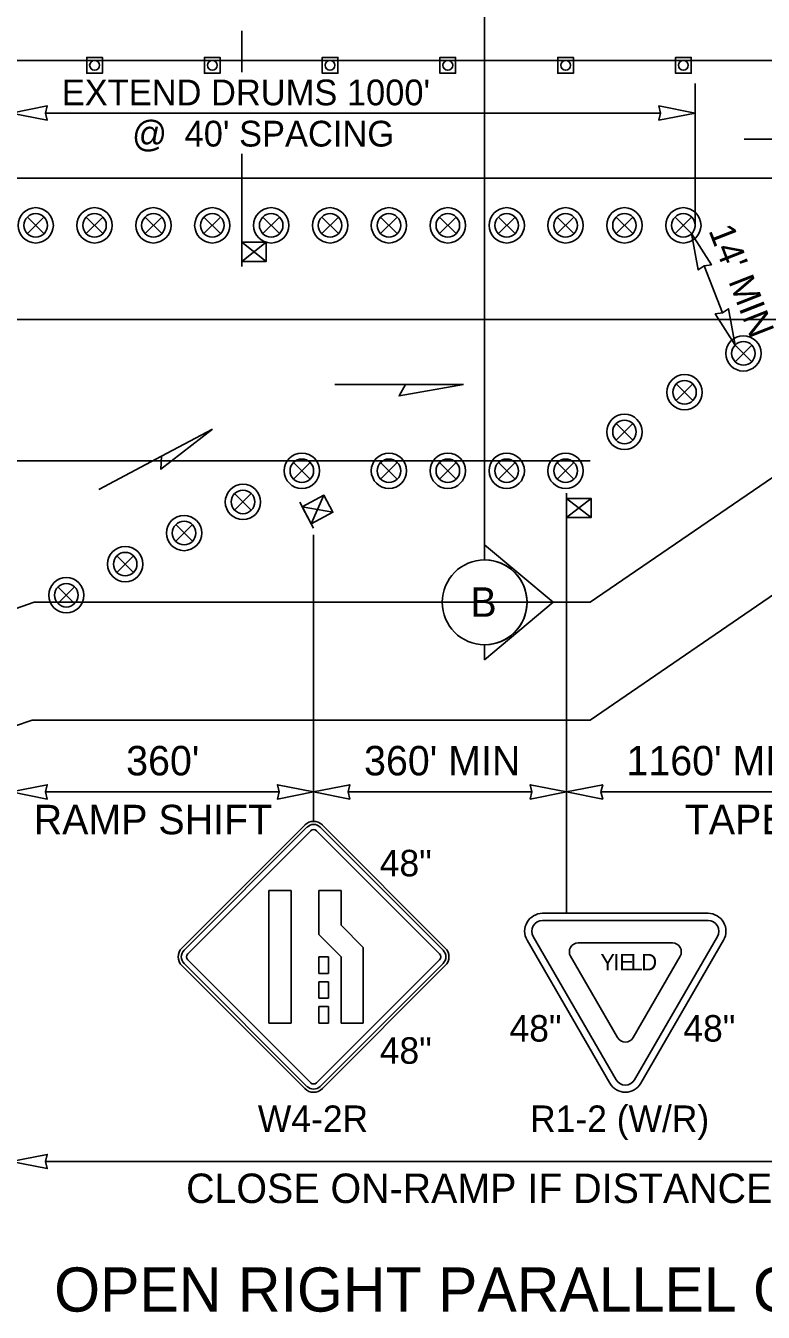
# Model space of a CAD drawing. Extents: x 99999 to 100116, y 99995 to 100013.
# Drawn here: x 100050.642 to 100052.647, y 100004.799 to 100008.293 of the extents above; entities that cross this region are included whole.
import ezdxf

# ---------------------------------------------------------------- set-up
doc = ezdxf.new("R2010")
doc.units = 0
for name, color, linetype in [('RD_MK_LineEdgeYellow', 7, 'Continuous'), ('RD_MK_LineLane', 7, 'Continuous'), ('SH_DE_DetailHeading2Text', 7, 'Continuous'), ('SH_GI_SectionCut', 7, 'Continuous'), ('TR_SN_ConstructionSigns', 7, 'Continuous'), ('TR_WZ_PortableSignMount5ftMinBlk-Org', 7, 'Continuous'), ('TR_WZ_PortableSignMount5ftMinRed-Wht', 7, 'Continuous'), ('TR_WZ_TrafficCone', 7, 'Continuous'), ('TR_WZ_TrafficSafetyDrum', 7, 'Continuous'), ('TR_WZ_WorkZoneDetails', 7, 'Continuous'), ('TR_WZ_WorkZoneTextCurrent', 7, 'Continuous')]:
    doc.layers.add(name, color=color, linetype=linetype)

msp = doc.modelspace()

# ---------------------------------------------------------------- linework, layer by layer
at = {"layer": 'RD_MK_LineEdgeYellow'}
for p, q in [((100048.195, 100007.8789), (100055.43, 100007.8789)), ((100052.1758, 100006.7269), (100052.7368, 100007.1109)), ((100050.6655, 100006.7269), (100048.195, 100005.8927)), ((100050.6655, 100006.7269), (100052.1758, 100006.7269))]:
    msp.add_line(p, q, dxfattribs=at)
at = {"layer": 'RD_MK_LineLane'}
for points in [[(100055.43, 100007.4949), (100048.195, 100007.4949)], [(100052.1758, 100007.1109), (100050.6024, 100007.1109)], [(100052.1758, 100007.1109), (100050.6024, 100007.1109)]]:
    msp.add_lwpolyline(points, dxfattribs=at)
at = {"layer": 'SH_GI_SectionCut'}
for p, q in [((100051.8894, 100008.3179), (100051.8894, 100006.8828)), ((100051.8894, 100006.8828), (100051.8894, 100006.8421)), ((100052.0755, 100006.7269), (100051.8894, 100006.8828)), ((100051.8894, 100006.571), (100052.0755, 100006.7269)), ((100051.8894, 100006.6117), (100051.8894, 100006.571))]:
    msp.add_line(p, q, dxfattribs=at)
msp.add_circle((100051.8894, 100006.7269), 0.1152, dxfattribs=at)
for start, end in [(0, 269.9978), (269.9978, 90.0022), (269.9978, 0)]:
    msp.add_arc((100051.8894, 100006.7269), 0.1152, start, end, dxfattribs=at)
at = {"layer": 'TR_SN_ConstructionSigns'}
for p, q in [((100051.4008, 100006.122), (100051.0667, 100005.7879)), ((100051.4067, 100006.1161), (100051.0726, 100005.7819)), ((100051.7766, 100005.7819), (100051.4425, 100006.1161)), ((100051.7826, 100005.7879), (100051.4485, 100006.122)), ((100051.0826, 100005.772), (100051.4167, 100006.1061)), ((100051.4326, 100006.1061), (100051.7667, 100005.772)), ((100051.303, 100005.944), (100051.3634, 100005.944)), ((100051.303, 100005.584), (100051.303, 100005.944)), ((100051.3634, 100005.944), (100051.303, 100005.944)), ((100051.303, 100005.944), (100051.303, 100005.584)), ((100051.3634, 100005.944), (100051.3634, 100005.584)), ((100051.3634, 100005.584), (100051.3634, 100005.944)), ((100051.4387, 100005.944), (100051.4992, 100005.944)), ((100051.4387, 100005.8245), (100051.4387, 100005.944)), ((100051.4992, 100005.944), (100051.4387, 100005.944)), ((100051.4387, 100005.944), (100051.4387, 100005.8245)), ((100051.4992, 100005.944), (100051.4992, 100005.8496)), ((100051.4992, 100005.8496), (100051.4992, 100005.944)), ((100052.4966, 100005.8822), (100052.0469, 100005.8822)), ((100051.4992, 100005.8496), (100051.5596, 100005.7891)), ((100051.5596, 100005.7891), (100051.4992, 100005.8496)), ((100052.0469, 100005.8627), (100052.0469, 100005.8629)), ((100052.0469, 100005.8629), (100052.2718, 100005.8629)), ((100052.2718, 100005.8629), (100052.0469, 100005.8629)), ((100052.0469, 100005.8629), (100052.0469, 100005.8627)), ((100051.4992, 100005.764), (100051.4387, 100005.8245)), ((100051.4387, 100005.8245), (100051.4992, 100005.764)), ((100052.2296, 100005.4205), (100052.0048, 100005.8091)), ((100052.0048, 100005.8091), (100052.2296, 100005.4205)), ((100052.2465, 100005.4302), (100052.0216, 100005.8189)), ((100052.0216, 100005.8189), (100052.2465, 100005.4302)), ((100052.2718, 100005.802), (100052.144, 100005.802)), ((100052.144, 100005.802), (100052.2718, 100005.802)), ((100052.3995, 100005.802), (100052.2718, 100005.802)), ((100052.2718, 100005.802), (100052.3995, 100005.802)), ((100052.5219, 100005.8189), (100052.2971, 100005.4303)), ((100052.2971, 100005.4303), (100052.5219, 100005.8189)), ((100052.5387, 100005.8091), (100052.3139, 100005.4205)), ((100052.3139, 100005.4205), (100052.5387, 100005.8091)), ((100051.5596, 100005.7891), (100051.5596, 100005.584)), ((100051.5596, 100005.584), (100051.5596, 100005.7891)), ((100051.0667, 100005.7402), (100051.4008, 100005.4061)), ((100051.0726, 100005.7462), (100051.4067, 100005.412)), ((100051.4167, 100005.422), (100051.0826, 100005.7561)), ((100051.7667, 100005.7561), (100051.4326, 100005.422)), ((100051.4387, 100005.764), (100051.4654, 100005.764)), ((100051.4387, 100005.719), (100051.4387, 100005.764)), ((100051.4654, 100005.764), (100051.4387, 100005.764)), ((100051.4387, 100005.764), (100051.4387, 100005.719)), ((100051.4425, 100005.412), (100051.7766, 100005.7462)), ((100051.4485, 100005.4061), (100051.7826, 100005.7402)), ((100051.4654, 100005.764), (100051.4654, 100005.719)), ((100051.4654, 100005.719), (100051.4654, 100005.764)), ((100051.4992, 100005.584), (100051.4992, 100005.764)), ((100051.4992, 100005.764), (100051.4992, 100005.584)), ((100052.1229, 100005.7654), (100052.2507, 100005.5445)), ((100052.2507, 100005.5445), (100052.1229, 100005.7654)), ((100052.2928, 100005.5445), (100052.4206, 100005.7654)), ((100052.4206, 100005.7654), (100052.2928, 100005.5445)), ((100051.4654, 100005.719), (100051.4387, 100005.719)), ((100051.4387, 100005.719), (100051.4654, 100005.719)), ((100051.4387, 100005.6965), (100051.4654, 100005.6965)), ((100051.4387, 100005.6515), (100051.4387, 100005.6965)), ((100051.4654, 100005.6965), (100051.4387, 100005.6965)), ((100051.4387, 100005.6965), (100051.4387, 100005.6515)), ((100051.4654, 100005.6965), (100051.4654, 100005.6515)), ((100051.4654, 100005.6515), (100051.4654, 100005.6965)), ((100051.4654, 100005.6515), (100051.4387, 100005.6515)), ((100051.4387, 100005.6515), (100051.4654, 100005.6515)), ((100051.4387, 100005.629), (100051.4654, 100005.629)), ((100051.4387, 100005.584), (100051.4387, 100005.629)), ((100051.4654, 100005.629), (100051.4387, 100005.629)), ((100051.4387, 100005.629), (100051.4387, 100005.584)), ((100051.4654, 100005.629), (100051.4654, 100005.584)), ((100051.4654, 100005.584), (100051.4654, 100005.629)), ((100051.3634, 100005.584), (100051.303, 100005.584)), ((100051.303, 100005.584), (100051.3634, 100005.584)), ((100051.4654, 100005.584), (100051.4387, 100005.584)), ((100051.4387, 100005.584), (100051.4654, 100005.584)), ((100051.5596, 100005.584), (100051.4992, 100005.584)), ((100051.4992, 100005.584), (100051.5596, 100005.584))]:
    msp.add_line(p, q, dxfattribs=at)
for points in [[(100052.0469, 100005.8822), (100052.4966, 100005.8822)], [(100052.2718, 100005.8629), (100052.4966, 100005.8629), (100052.4966, 100005.8627)], [(100052.4966, 100005.8627), (100052.4966, 100005.8629), (100052.2718, 100005.8629)]]:
    msp.add_lwpolyline(points, dxfattribs=at)
for centre, radius, start, end in [((100051.4246, 100006.0982), 0.0338, 45, 135), ((100051.4246, 100006.0982), 0.0253, 45, 135), ((100051.4246, 100006.0982), 0.0113, 45, 135), ((100052.0469, 100005.8335), 0.0487, 90, 210.0517), ((100052.0469, 100005.8335), 0.0487, 90, 210.0517), ((100052.4966, 100005.8335), 0.0487, 329.9522, 90), ((100052.4966, 100005.8335), 0.0487, 329.9522, 90), ((100052.0469, 100005.8335), 0.0292, 90, 210.0517), ((100052.0469, 100005.8335), 0.0292, 90, 210.0517), ((100052.4966, 100005.8335), 0.0292, 329.9522, 90), ((100052.4966, 100005.8335), 0.0292, 329.9522, 90), ((100052.144, 100005.7776), 0.0244, 90, 210.0513), ((100052.144, 100005.7776), 0.0244, 90, 210.0513), ((100052.3995, 100005.7776), 0.0244, 329.9514, 90), ((100052.3995, 100005.7776), 0.0244, 329.9514, 90), ((100051.0905, 100005.764), 0.0338, 135, 225), ((100051.0905, 100005.764), 0.0253, 135, 225), ((100051.0905, 100005.764), 0.0113, 135, 225), ((100051.7587, 100005.764), 0.0113, 315, 45), ((100051.7587, 100005.764), 0.0253, 315, 45), ((100051.7587, 100005.764), 0.0338, 315, 45), ((100052.2718, 100005.5567), 0.0244, 210.0519, 329.9525), ((100052.2718, 100005.5567), 0.0244, 210.0519, 329.9525), ((100051.4246, 100005.4299), 0.0113, 225, 315), ((100052.2718, 100005.4449), 0.0487, 210.0518, 329.9516), ((100052.2718, 100005.4449), 0.0487, 210.0518, 329.9516), ((100052.2718, 100005.4449), 0.0292, 210.0518, 329.9516), ((100052.2718, 100005.4449), 0.0292, 210.0518, 329.9516), ((100051.4246, 100005.4299), 0.0338, 225, 315), ((100051.4246, 100005.4299), 0.0253, 225, 315)]:
    msp.add_arc(centre, radius, start, end, dxfattribs=at)
at = {"layer": 'TR_WZ_PortableSignMount5ftMinBlk-Org'}
for p, q in [((100051.2294, 100007.6389), (100051.2294, 100007.7189)), ((100051.2961, 100007.7049), (100051.2294, 100007.6529)), ((100051.2961, 100007.6529), (100051.2294, 100007.7049)), ((100051.2627, 100007.6789), (100051.2627, 100007.6789)), ((100051.2628, 100007.679), (100051.2628, 100007.679)), ((100051.4246, 100006.9281), (100051.3873, 100006.9988)), ((100051.4528, 100007.0176), (100051.4181, 100006.9405)), ((100051.4771, 100006.9716), (100051.3938, 100006.9865)), ((100051.4354, 100006.9791), (100051.4354, 100006.9791)), ((100051.4355, 100006.9792), (100051.4355, 100006.9792))]:
    msp.add_line(p, q, dxfattribs=at)
for points in [[(100051.2961, 100007.7049), (100051.2961, 100007.6529), (100051.2294, 100007.6529), (100051.2294, 100007.7049)], [(100051.2294, 100007.6529), (100051.2961, 100007.6529), (100051.2961, 100007.7049), (100051.2294, 100007.7049)], [(100051.4528, 100007.0176), (100051.4771, 100006.9716), (100051.4181, 100006.9405), (100051.3938, 100006.9865)], [(100051.4181, 100006.9405), (100051.4771, 100006.9716), (100051.4528, 100007.0176), (100051.3938, 100006.9865)]]:
    msp.add_lwpolyline(points, close=True, dxfattribs=at)
at = {"layer": 'TR_WZ_PortableSignMount5ftMinRed-Wht'}
for p, q in [((100052.1119, 100006.9432), (100052.1119, 100007.0232)), ((100052.1786, 100007.0092), (100052.1119, 100006.9572)), ((100052.1786, 100006.9572), (100052.1119, 100007.0092)), ((100052.1452, 100006.9832), (100052.1452, 100006.9832)), ((100052.1453, 100006.9832), (100052.1453, 100006.9832))]:
    msp.add_line(p, q, dxfattribs=at)
for points in [[(100052.1786, 100007.0092), (100052.1786, 100006.9572), (100052.1119, 100006.9572), (100052.1119, 100007.0092)], [(100052.1119, 100006.9572), (100052.1786, 100006.9572), (100052.1786, 100007.0092), (100052.1119, 100007.0092)]]:
    msp.add_lwpolyline(points, close=True, dxfattribs=at)
at = {"layer": 'TR_WZ_TrafficCone'}
for points in [[(100050.8081, 100008.2069), (100050.8507, 100008.2069), (100050.8507, 100008.1642), (100050.8081, 100008.1642), (100050.8081, 100008.2069)], [(100050.8081, 100008.1642), (100050.8507, 100008.1642), (100050.8507, 100008.2069), (100050.8081, 100008.2069), (100050.8081, 100008.1642)], [(100051.1281, 100008.2069), (100051.1707, 100008.2069), (100051.1707, 100008.1642), (100051.1281, 100008.1642), (100051.1281, 100008.2069)], [(100051.1281, 100008.1642), (100051.1707, 100008.1642), (100051.1707, 100008.2069), (100051.1281, 100008.2069), (100051.1281, 100008.1642)], [(100051.4481, 100008.2069), (100051.4907, 100008.2069), (100051.4907, 100008.1642), (100051.4481, 100008.1642), (100051.4481, 100008.2069)], [(100051.4481, 100008.1642), (100051.4907, 100008.1642), (100051.4907, 100008.2069), (100051.4481, 100008.2069), (100051.4481, 100008.1642)], [(100051.7681, 100008.2069), (100051.8107, 100008.2069), (100051.8107, 100008.1642), (100051.7681, 100008.1642), (100051.7681, 100008.2069)], [(100051.7681, 100008.1642), (100051.8107, 100008.1642), (100051.8107, 100008.2069), (100051.7681, 100008.2069), (100051.7681, 100008.1642)], [(100052.0881, 100008.2069), (100052.1307, 100008.2069), (100052.1307, 100008.1642), (100052.0881, 100008.1642), (100052.0881, 100008.2069)], [(100052.0881, 100008.1642), (100052.1307, 100008.1642), (100052.1307, 100008.2069), (100052.0881, 100008.2069), (100052.0881, 100008.1642)], [(100052.4081, 100008.2069), (100052.4507, 100008.2069), (100052.4507, 100008.1642), (100052.4081, 100008.1642), (100052.4081, 100008.2069)], [(100052.4081, 100008.1642), (100052.4507, 100008.1642), (100052.4507, 100008.2069), (100052.4081, 100008.2069), (100052.4081, 100008.1642)]]:
    msp.add_lwpolyline(points, dxfattribs=at)
for centre in [(100050.8294, 100008.1856), (100051.1494, 100008.1856), (100051.4694, 100008.1856), (100051.7894, 100008.1856), (100052.1094, 100008.1856), (100052.4294, 100008.1856)]:
    msp.add_circle(centre, 0.0133, dxfattribs=at)
at = {"layer": 'TR_WZ_TrafficSafetyDrum'}
for p, q in [((100050.6468, 100007.7735), (100050.692, 100007.7283)), ((100050.692, 100007.7735), (100050.6468, 100007.7283)), ((100050.8068, 100007.7735), (100050.852, 100007.7283)), ((100050.852, 100007.7735), (100050.8068, 100007.7283)), ((100050.9668, 100007.7735), (100051.012, 100007.7283)), ((100051.012, 100007.7735), (100050.9668, 100007.7283)), ((100051.1268, 100007.7735), (100051.172, 100007.7283)), ((100051.172, 100007.7735), (100051.1268, 100007.7283)), ((100051.2868, 100007.7735), (100051.332, 100007.7283)), ((100051.332, 100007.7735), (100051.2868, 100007.7283)), ((100051.4468, 100007.7735), (100051.492, 100007.7283)), ((100051.492, 100007.7735), (100051.4468, 100007.7283)), ((100051.6068, 100007.7735), (100051.652, 100007.7283)), ((100051.652, 100007.7735), (100051.6068, 100007.7283)), ((100051.7668, 100007.7735), (100051.812, 100007.7283)), ((100051.812, 100007.7735), (100051.7668, 100007.7283)), ((100051.9268, 100007.7735), (100051.972, 100007.7283)), ((100051.972, 100007.7735), (100051.9268, 100007.7283)), ((100052.0868, 100007.7735), (100052.132, 100007.7283)), ((100052.132, 100007.7735), (100052.0868, 100007.7283)), ((100052.2468, 100007.7735), (100052.292, 100007.7283)), ((100052.292, 100007.7735), (100052.2468, 100007.7283)), ((100052.4068, 100007.7735), (100052.452, 100007.7283)), ((100052.452, 100007.7735), (100052.4068, 100007.7283)), ((100052.57, 100007.4257), (100052.6153, 100007.3805)), ((100052.6153, 100007.4257), (100052.57, 100007.3805)), ((100052.41, 100007.3201), (100052.4553, 100007.2749)), ((100052.4553, 100007.3201), (100052.41, 100007.2749)), ((100052.2468, 100007.2124), (100052.292, 100007.1672)), ((100052.292, 100007.2124), (100052.2468, 100007.1672)), ((100051.37, 100007.1069), (100051.4153, 100007.0616)), ((100051.4153, 100007.1069), (100051.37, 100007.0616)), ((100051.6068, 100007.1069), (100051.652, 100007.0616)), ((100051.652, 100007.1069), (100051.6068, 100007.0616)), ((100051.7668, 100007.1069), (100051.812, 100007.0616)), ((100051.812, 100007.1069), (100051.7668, 100007.0616)), ((100051.9268, 100007.1069), (100051.972, 100007.0616)), ((100051.972, 100007.1069), (100051.9268, 100007.0616)), ((100052.0868, 100007.1069), (100052.132, 100007.0616)), ((100052.132, 100007.1069), (100052.0868, 100007.0616)), ((100051.21, 100007.0224), (100051.2553, 100006.9771)), ((100051.2553, 100007.0224), (100051.21, 100006.9771)), ((100051.05, 100006.9379), (100051.0953, 100006.8926)), ((100051.0953, 100006.9379), (100051.05, 100006.8926)), ((100050.89, 100006.8534), (100050.9353, 100006.8081)), ((100050.9353, 100006.8534), (100050.89, 100006.8081)), ((100050.73, 100006.7689), (100050.7753, 100006.7236)), ((100050.7753, 100006.7689), (100050.73, 100006.7236))]:
    msp.add_line(p, q, dxfattribs=at)
for centre, radius in [((100050.6694, 100007.7509), 0.048), ((100050.6694, 100007.7509), 0.048), ((100050.8294, 100007.7509), 0.048), ((100050.8294, 100007.7509), 0.048), ((100050.9894, 100007.7509), 0.048), ((100050.9894, 100007.7509), 0.048), ((100051.1494, 100007.7509), 0.048), ((100051.1494, 100007.7509), 0.048), ((100051.3094, 100007.7509), 0.048), ((100051.3094, 100007.7509), 0.048), ((100051.4694, 100007.7509), 0.048), ((100051.4694, 100007.7509), 0.048), ((100051.6294, 100007.7509), 0.048), ((100051.6294, 100007.7509), 0.048), ((100051.7894, 100007.7509), 0.048), ((100051.7894, 100007.7509), 0.048), ((100051.9494, 100007.7509), 0.048), ((100051.9494, 100007.7509), 0.048), ((100052.1094, 100007.7509), 0.048), ((100052.1094, 100007.7509), 0.048), ((100052.2694, 100007.7509), 0.048), ((100052.2694, 100007.7509), 0.048), ((100052.4294, 100007.7509), 0.048), ((100052.4294, 100007.7509), 0.048), ((100050.6694, 100007.7509), 0.032), ((100050.8294, 100007.7509), 0.032), ((100050.9894, 100007.7509), 0.032), ((100051.1494, 100007.7509), 0.032), ((100051.3094, 100007.7509), 0.032), ((100051.4694, 100007.7509), 0.032), ((100051.6294, 100007.7509), 0.032), ((100051.7894, 100007.7509), 0.032), ((100051.9494, 100007.7509), 0.032), ((100052.1094, 100007.7509), 0.032), ((100052.2694, 100007.7509), 0.032), ((100052.4294, 100007.7509), 0.032), ((100052.5927, 100007.4031), 0.048), ((100052.5927, 100007.4031), 0.048), ((100052.5927, 100007.4031), 0.032), ((100052.4327, 100007.2975), 0.048), ((100052.4327, 100007.2975), 0.048), ((100052.4327, 100007.2975), 0.032), ((100052.2694, 100007.1898), 0.048), ((100052.2694, 100007.1898), 0.048), ((100052.2694, 100007.1898), 0.032), ((100051.3927, 100007.0842), 0.048), ((100051.3927, 100007.0842), 0.048), ((100051.6294, 100007.0842), 0.048), ((100051.6294, 100007.0842), 0.048), ((100051.7894, 100007.0842), 0.048), ((100051.7894, 100007.0842), 0.048), ((100051.9494, 100007.0842), 0.048), ((100051.9494, 100007.0842), 0.048), ((100052.1094, 100007.0842), 0.048), ((100052.1094, 100007.0842), 0.048), ((100051.3927, 100007.0842), 0.032), ((100051.6294, 100007.0842), 0.032), ((100051.7894, 100007.0842), 0.032), ((100051.9494, 100007.0842), 0.032), ((100052.1094, 100007.0842), 0.032), ((100051.2327, 100006.9997), 0.048), ((100051.2327, 100006.9997), 0.048), ((100051.2327, 100006.9997), 0.032), ((100051.0727, 100006.9152), 0.048), ((100051.0727, 100006.9152), 0.048), ((100051.0727, 100006.9152), 0.032), ((100050.9127, 100006.8307), 0.048), ((100050.9127, 100006.8307), 0.048), ((100050.9127, 100006.8307), 0.032), ((100050.7527, 100006.7462), 0.048), ((100050.7527, 100006.7462), 0.048), ((100050.7527, 100006.7462), 0.032)]:
    msp.add_circle(centre, radius, dxfattribs=at)
at = {"layer": 'TR_WZ_WorkZoneDetails'}
for p, q in [((100051.2294, 100008.1669), (100051.2294, 100008.2789)), ((100048.195, 100008.1989), (100055.43, 100008.1989)), ((100052.4614, 100008.1359), (100052.4614, 100007.7456)), ((100052.3676, 100008.0559), (100050.6962, 100008.0559)), ((100052.7876, 100007.985), (100052.5947, 100007.985)), ((100051.2294, 100007.7188), (100051.2294, 100007.9449)), ((100052.4861, 100007.6409), (100052.536, 100007.5131)), ((100051.6748, 100007.3183), (100051.4819, 100007.3183)), ((100051.0112, 100007.1238), (100050.8406, 100007.0337)), ((100052.1119, 100006.9512), (100052.1119, 100005.8822)), ((100051.4246, 100006.91), (100051.4246, 100006.1319)), ((100052.1758, 100006.4069), (100052.7368, 100006.7909)), ((100048.195, 100005.5689), (100050.6601, 100006.4069)), ((100050.6601, 100006.4069), (100052.1758, 100006.4069)), ((100050.6601, 100006.4069), (100052.1758, 100006.4069)), ((100051.3309, 100006.2119), (100050.6962, 100006.2119)), ((100052.0181, 100006.2119), (100051.5184, 100006.2119)), ((100053.0198, 100006.2119), (100052.2056, 100006.2119)), ((100054.3691, 100005.2082), (100050.6962, 100005.2082))]:
    msp.add_line(p, q, dxfattribs=at)
for points in [[(100050.6024, 100008.0559), (100050.7007, 100008.0751), (100050.6962, 100008.0559), (100050.7007, 100008.0366)], [(100052.4614, 100008.0559), (100052.3631, 100008.0751), (100052.3676, 100008.0559), (100052.3631, 100008.0366)], [(100052.452, 100007.7283), (100052.4701, 100007.6298), (100052.4863, 100007.6411), (100052.5059, 100007.6439)], [(100052.57, 100007.4257), (100052.5161, 100007.5101), (100052.5357, 100007.5129), (100052.552, 100007.5242)], [(100051.8321, 100007.3183), (100051.657, 100007.2875), (100051.6748, 100007.3183)], [(100051.1502, 100007.1972), (100051.0098, 100007.0882), (100051.0112, 100007.1238)], [(100050.6024, 100006.2119), (100050.7007, 100006.2312), (100050.6962, 100006.2119), (100050.7007, 100006.1926)], [(100051.4246, 100006.2119), (100051.3263, 100006.2312), (100051.3309, 100006.2119), (100051.3263, 100006.1926)], [(100051.4246, 100006.2119), (100051.5229, 100006.2312), (100051.5184, 100006.2119), (100051.5229, 100006.1926)], [(100052.1119, 100006.2119), (100052.0136, 100006.2312), (100052.0181, 100006.2119), (100052.0136, 100006.1926)], [(100052.1119, 100006.2119), (100052.2102, 100006.2312), (100052.2056, 100006.2119), (100052.2102, 100006.1926)], [(100050.6024, 100005.2082), (100050.7007, 100005.2275), (100050.6962, 100005.2082), (100050.7007, 100005.1889)]]:
    msp.add_lwpolyline(points, close=True, dxfattribs=at)

# ---------------------------------------------------------------- texts
at = {"layer": 'SH_DE_DetailHeading2Text'}
msp.add_text('OPEN RIGHT PARALLEL ON-RAMP DETAIL', height=0.12, rotation=360, dxfattribs=at).set_placement((100050.7196, 100004.8003))
at = {"layer": 'SH_GI_SectionCut'}
msp.add_text('B', height=0.08, rotation=359.99, dxfattribs=at).set_placement((100051.8507, 100006.6876))
at = {"layer": 'TR_SN_ConstructionSigns'}
for s, p in [('48"', (100051.6044, 100005.9826)), ('48"', (100052.4295, 100005.5337)), ('48"', (100051.6044, 100005.4735)), ('W4-2R', (100051.2732, 100005.2882)), ('R1-2 (W/R)', (100052.013, 100005.2882))]:
    msp.add_text(s, height=0.072, rotation=360, dxfattribs=at).set_placement(p)
for s, height, p in [('Y', 0.045, (100052.2036, 100005.7271)), ('I', 0.045, (100052.2387, 100005.7271)), ('E', 0.045, (100052.2549, 100005.7271)), ('L', 0.045, (100052.2855, 100005.7271)), ('D', 0.045, (100052.3147, 100005.7271)), ('48"', 0.072, (100051.9571, 100005.5337))]:
    msp.add_text(s, height=height, dxfattribs=at).set_placement(p)
at = {"layer": 'TR_WZ_WorkZoneTextCurrent'}
for s, height, p in [("EXTEND DRUMS 1000'", 0.07, (100050.7402, 100008.0769)), ('@', 0.07, (100050.9313, 100007.9649)), ("40' SPACING", 0.07, (100051.0741, 100007.9649)), ("360'", 0.08, (100050.9153, 100006.2569)), ("360' MIN", 0.08, (100051.5618, 100006.2569)), ("1160' MERGE", 0.08, (100052.2749, 100006.2569)), ('RAMP SHIFT', 0.08, (100050.6641, 100006.0969)), ('TAPER', 0.08, (100052.4332, 100006.0969)), ('CLOSE ON-RAMP IF DISTANCE IS NOT AVAILABLE', 0.08, (100051.0782, 100005.0953))]:
    msp.add_text(s, height=height, dxfattribs=at).set_placement(p)
msp.add_text("14' MIN", height=0.07, rotation=291.3231, dxfattribs=at).set_placement((100052.497, 100007.7371))

doc.saveas('drawing.dxf')
